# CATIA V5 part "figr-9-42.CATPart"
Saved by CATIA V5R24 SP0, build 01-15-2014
Part number: Part1
Bounding box of the stored display mesh (mm): x -60 to 60, y -70.383 to 65.913, z 0 to 125
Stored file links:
  D:\KAVITA\CATIA V5-6R2014 Project_ Kavita\CATIA V5-6R2014_partfiles\Partfiles\c09_catia_v5-6r2014_prt\figr-9-42.CATPart
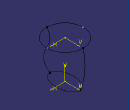
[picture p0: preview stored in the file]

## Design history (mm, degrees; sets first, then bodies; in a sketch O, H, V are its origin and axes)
Set1
  Plane1: type Offset, RefPlane xy-plane, Offset 125
Body1 (main body)
  Sketch1 on xy-plane, origin (0, 0, 0), H (1, 0, 0), V (0, 1, 0)
    ellipse A1 centre (0, 0) semi-axes 50, 30 rotation 270
    point P1 (30, 0)
    coincidence: P1 H, A1 P1
  Sketch2 on Plane1, origin (0, 0, 125), H (1, 0, 0), V (0, 1, 0)
    circle A1 centre (0, 0) radius 60
  Sketch3 on yz-plane, origin (0, 0, 0), H (0, 1, 0), V (0, 0, 1)
    arc A1 centre (-129.6632, 77.2731) radius 195.5761 from (50, 0) to (60, 125) ccw
    point P2 (50, 0)
    point P3 (60, 125)
    reference projected line E1 (-50, 0) -> (50, 0) from edge of Sketch1
    reference projected line E2 (-60, 125) -> (60, 125) from edge of Sketch2
    coincidence: P2 H, P2 E1, P3 E2
  Sketch4 on yz-plane, origin (0, 0, 0), H (0, 1, 0), V (0, 0, 1)
    spline S1 through (-50, 0) (-70, 40) (-50, 100) (-60, 125)
    reference projected line E1 (-60, 125) -> (60, 125) from edge of Sketch2
    reference projected line E2 (-50, 0) -> (50, 0) from edge of Sketch1
    point P1 (-60, 125)
    point P2 (-50, 0)
    coincidence: P1 E1, P2 E2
